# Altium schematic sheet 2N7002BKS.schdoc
size 127 x 101 mm
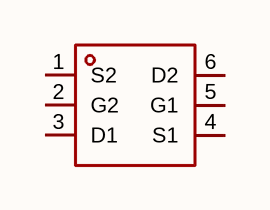
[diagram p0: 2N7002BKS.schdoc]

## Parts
Q?  2n7002bks  [SOT-363_L2.0-W1.3-P0.65-LS2.1-BL]  (value not drawn)

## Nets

Not connected (* = marked no-connect by the designer): Q? 1(S2) 2(G2) 3(D1) 4(S1) 5(G1) 6(D2)

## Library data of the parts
Q? = 2n7002bks: 数量:2个N沟道;漏源电压(Vdss):60V;连续漏极电流(Id):300mA;导通电阻(RDS(on)):2.5Ω@10V;耗散功率(Pd):350mW;阈值电压(Vgs(th)):2.5V@250uA;; Manufacturer: TECH PUBLIC(台舟); AddInBom: yes; ModelId: ea15c7b026c54341854a7f0d9614aed9; ModelName: SOT-363-6P_L2.0-W1.3-H1.1-LS2.0-P0.65; ModelTransform: 83.17133,78.74,0,90,0,0,0,0,0; Number: 2个N沟道; Drain to Source Voltage: 60V; Current - Continuous Drain(Id): 300mA; Pd - Power Dissipation: 350mW; Gate Charge(Qg): 3nC@10V; Input Capacitance(Ciss): 27pF; Reverse Transfer Capacitance (Crss@Vds): 2pF; Type: N沟道; Output Capacitance(Coss): 18pF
